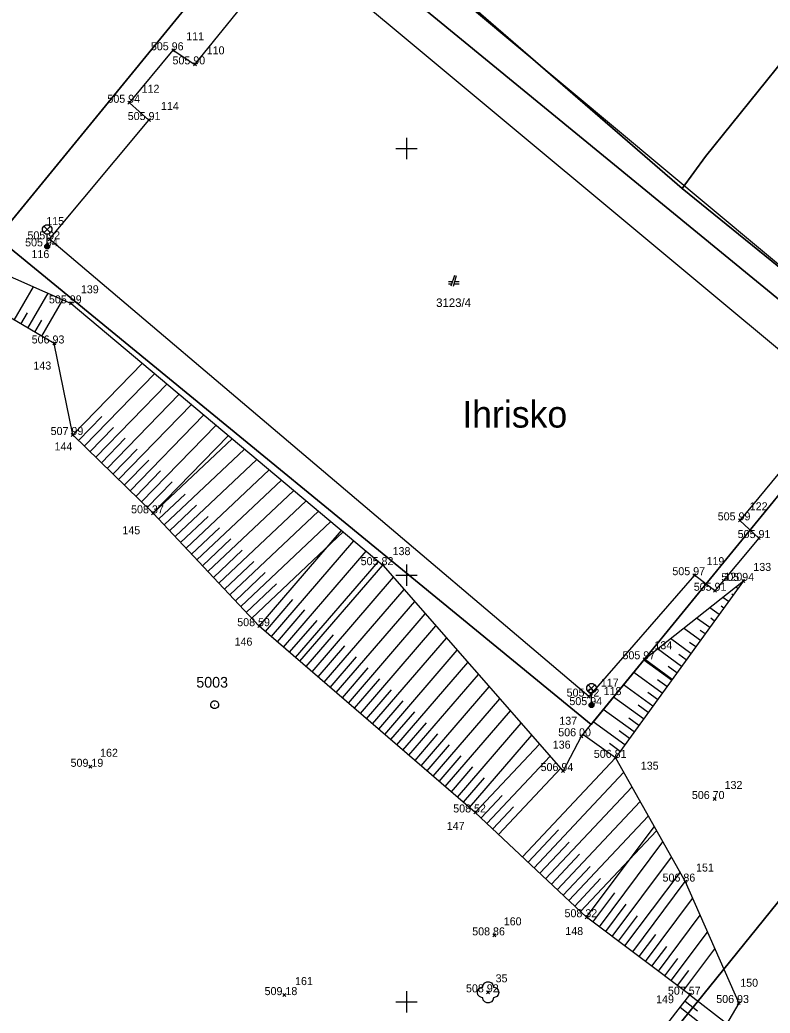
# Model space of a CAD drawing. Extents: x -408550 to -407654, y -1233019 to -1231230.
# Drawn here: x -407958.14 to -407922.95, y -1232060.52 to -1232013.97 of the extents above; entities that cross this region are included whole.
import ezdxf

# ---------------------------------------------------------------- set-up
doc = ezdxf.new("R2010")
doc.units = 0
for name, color, linetype in [('Level 1', 7, 'Continuous'), ('Level 12', 7, 'Continuous'), ('Level 13', 7, 'Continuous'), ('Level 16', 7, 'Continuous'), ('Level 23', 7, 'Continuous'), ('Level 26', 7, 'Continuous'), ('Level 28', 7, 'Continuous'), ('Level 30', 7, 'Continuous'), ('Level 40', 7, 'Continuous'), ('Level 41', 7, 'Continuous'), ('Level 45', 7, 'Continuous')]:
    doc.layers.add(name, color=color, linetype=linetype)

msp = doc.modelspace()

# ---------------------------------------------------------------- linework, layer by layer
at = {"layer": 'Level 1'}
for p, q in [((-407940, -1232019.5), (-407940, -1232020.5)), ((-407940.5, -1232020), (-407939.5, -1232020)), ((-407940, -1232039.5), (-407940, -1232040.5)), ((-407940.5, -1232040), (-407939.5, -1232040)), ((-407940, -1232059.5), (-407940, -1232060.5)), ((-407940.5, -1232060), (-407939.5, -1232060))]:
    msp.add_line(p, q, dxfattribs=at)
for points in [[(-408002.95, -1231959.78), (-407998.58, -1231963.3), (-407985.37, -1231974.5), (-407975.08, -1231982.73), (-407972.21, -1231984.54), (-407969.45, -1231986.76), (-407966.11, -1231989.44), (-407955.64, -1231997.88), (-407939.09, -1232011.47), (-407927.08, -1232021.88), (-407908.02, -1232037.31)], [(-407865.11, -1232098.76), (-407959.41, -1232100.85), (-407908.02, -1232037.31), (-407927.08, -1232021.88), (-407925.98, -1232020.38), (-407922.27, -1232015.79), (-407913.48, -1232004.91), (-407905.89, -1231995.51), (-407896.46, -1231983.85)], [(-407937.755, -1232025.95), (-407937.93, -1232026.45)], [(-407937.805, -1232026.45), (-407937.655, -1232025.95)], [(-407937.86, -1232026.25), (-407938.03, -1232026.25)], [(-407938.03, -1232026.35), (-407937.895, -1232026.35)], [(-407937.775, -1232026.35), (-407937.53, -1232026.35)], [(-407937.53, -1232026.25), (-407937.745, -1232026.25)], [(-407908.02, -1232037.31), (-407959.41, -1232100.85), (-407964.75, -1232098.99), (-407974.67, -1232095.53), (-407985.8, -1232091.65), (-408004.8, -1232085.03), (-408023.96, -1232078.34), (-408035.27, -1232074.4), (-408044.77, -1232071.09)]]:
    msp.add_lwpolyline(points, dxfattribs=at)
for points in [[(-407908.98, -1231973.85), (-407908.6, -1231973.38), (-407908.02, -1231973.41), (-407904.44, -1231976.23), (-407900.26, -1231979.53), (-407895.94, -1231983.2), (-407896.46, -1231983.85), (-407905.89, -1231995.51), (-407913.48, -1232004.91), (-407922.27, -1232015.79), (-407925.98, -1232020.38), (-407927.08, -1232021.88), (-407939.09, -1232011.47)], [(-407945.9, -1232007.95), (-407918.05, -1232030.75), (-407931.35, -1232047), (-407959.2, -1232024.19)], [(-407918.05, -1232030.75), (-407945.9, -1232007.95), (-407959.2, -1232024.19), (-407931.35, -1232047)]]:
    msp.add_lwpolyline(points, close=True, dxfattribs=at)
at = {"layer": 'Level 12'}
msp.add_lwpolyline([(-408056.73, -1232038.31), (-408035.18, -1232049.43), (-408016.67, -1232058.98), (-407995.64, -1232070.23), (-407983.94, -1232082.87), (-407968.55, -1232099.65), (-407955.47, -1232103.17), (-407935.56, -1232108.32), (-407927.78, -1232110.15), (-407922.43, -1232090.45), (-407918.07, -1232073.76), (-407912.71, -1232053.79), (-407910.82, -1232047.19), (-407908.67, -1232042.13), (-407906.88, -1232038.31), (-407908.34, -1232037.12), (-407921.23, -1232026.55), (-407939.09, -1232011.64)], dxfattribs=at)
at = {"layer": 'Level 13'}
for p, q in [((-407958.413, -1232028.044), (-407957.504, -1232026.481)), ((-407957.765, -1232028.421), (-407956.814, -1232026.786)), ((-407957.117, -1232028.799), (-407956.123, -1232027.091)), ((-407958.089, -1232028.233), (-407957.779, -1232027.7)), ((-407957.441, -1232028.61), (-407957.117, -1232028.053)), ((-407955.66, -1232033.43), (-407952.39, -1232030.071)), ((-407955.123, -1232033.953), (-407951.814, -1232030.555)), ((-407954.585, -1232034.476), (-407951.238, -1232031.038)), ((-407954.048, -1232034.999), (-407950.662, -1232031.522)), ((-407953.51, -1232035.523), (-407950.086, -1232032.005)), ((-407955.391, -1232033.692), (-407954.296, -1232032.567)), ((-407952.973, -1232036.046), (-407949.51, -1232032.489)), ((-407954.854, -1232034.215), (-407953.746, -1232033.076)), ((-407952.436, -1232036.569), (-407948.934, -1232032.972)), ((-407954.316, -1232034.738), (-407953.196, -1232033.586)), ((-407951.898, -1232037.092), (-407948.358, -1232033.455)), ((-407951.89, -1232037.1), (-407948.179, -1232033.606)), ((-407953.779, -1232035.261), (-407952.645, -1232034.096)), ((-407951.376, -1232037.646), (-407947.6, -1232034.092)), ((-407953.242, -1232035.784), (-407952.095, -1232034.606)), ((-407950.862, -1232038.192), (-407947.022, -1232034.577)), ((-407952.704, -1232036.307), (-407951.545, -1232035.116)), ((-407950.348, -1232038.738), (-407946.443, -1232035.062)), ((-407952.167, -1232036.831), (-407950.994, -1232035.626)), ((-407949.834, -1232039.284), (-407945.865, -1232035.548)), ((-407951.633, -1232037.373), (-407950.386, -1232036.199)), ((-407949.32, -1232039.83), (-407945.286, -1232036.033)), ((-407948.805, -1232040.377), (-407944.708, -1232036.519)), ((-407951.119, -1232037.919), (-407949.851, -1232036.725)), ((-407948.291, -1232040.923), (-407944.129, -1232037.004)), ((-407950.605, -1232038.465), (-407949.315, -1232037.251)), ((-407947.777, -1232041.469), (-407943.551, -1232037.49)), ((-407950.091, -1232039.011), (-407948.78, -1232037.777)), ((-407947.263, -1232042.015), (-407942.972, -1232037.975)), ((-407946.91, -1232042.39), (-407943.05, -1232037.911)), ((-407949.577, -1232039.557), (-407948.244, -1232038.303)), ((-407946.342, -1232042.88), (-407942.475, -1232038.393)), ((-407949.063, -1232040.103), (-407947.709, -1232038.829)), ((-407945.774, -1232043.369), (-407941.901, -1232038.875)), ((-407948.548, -1232040.65), (-407947.173, -1232039.355)), ((-407945.206, -1232043.859), (-407941.326, -1232039.357)), ((-407948.034, -1232041.196), (-407946.638, -1232039.881)), ((-407945.002, -1232044.034), (-407941.12, -1232039.53)), ((-407944.434, -1232044.524), (-407940.621, -1232040.1)), ((-407947.52, -1232041.742), (-407946.102, -1232040.407)), ((-407943.866, -1232045.014), (-407940.121, -1232040.669)), ((-407924.461, -1232040.63), (-407924.562, -1232040.557)), ((-407946.626, -1232042.635), (-407945.339, -1232041.142)), ((-407943.297, -1232045.503), (-407939.622, -1232041.239)), ((-407924.901, -1232041.237), (-407925.173, -1232041.04)), ((-407924.681, -1232040.934), (-407924.743, -1232040.889)), ((-407946.058, -1232043.124), (-407944.769, -1232041.629)), ((-407925.341, -1232041.845), (-407925.785, -1232041.523)), ((-407925.121, -1232041.541), (-407925.24, -1232041.455)), ((-407945.49, -1232043.614), (-407944.199, -1232042.116)), ((-407942.729, -1232045.993), (-407939.123, -1232041.808)), ((-407925.782, -1232042.452), (-407926.396, -1232042.007)), ((-407925.562, -1232042.148), (-407925.738, -1232042.021)), ((-407942.161, -1232046.482), (-407938.624, -1232042.378)), ((-407926.222, -1232043.059), (-407927.007, -1232042.49)), ((-407926.002, -1232042.755), (-407926.235, -1232042.587)), ((-407944.718, -1232044.279), (-407943.437, -1232042.793)), ((-407941.593, -1232046.972), (-407938.124, -1232042.947)), ((-407926.662, -1232043.666), (-407927.618, -1232042.973)), ((-407926.442, -1232043.363), (-407926.732, -1232043.152)), ((-407944.15, -1232044.769), (-407942.891, -1232043.309)), ((-407941.025, -1232047.462), (-407937.625, -1232043.517)), ((-407927.102, -1232044.273), (-407928.229, -1232043.457)), ((-407943.582, -1232045.258), (-407942.346, -1232043.825)), ((-407940.457, -1232047.951), (-407937.126, -1232044.086)), ((-407927.569, -1232044.917), (-407928.868, -1232043.975)), ((-407927.543, -1232044.881), (-407928.84, -1232043.94)), ((-407926.882, -1232043.97), (-407927.229, -1232043.718)), ((-407943.013, -1232045.748), (-407941.801, -1232044.341)), ((-407928.009, -1232045.524), (-407929.345, -1232044.556)), ((-407927.322, -1232044.577), (-407927.726, -1232044.284)), ((-407942.445, -1232046.238), (-407941.256, -1232044.857)), ((-407939.889, -1232048.441), (-407936.626, -1232044.656)), ((-407927.789, -1232045.22), (-407928.228, -1232044.902)), ((-407941.877, -1232046.727), (-407940.711, -1232045.374)), ((-407939.321, -1232048.931), (-407936.127, -1232045.225)), ((-407928.449, -1232046.131), (-407929.821, -1232045.137)), ((-407928.229, -1232045.828), (-407928.68, -1232045.501)), ((-407941.309, -1232047.217), (-407940.165, -1232045.89)), ((-407938.752, -1232049.42), (-407935.628, -1232045.795)), ((-407928.889, -1232046.738), (-407930.297, -1232045.718)), ((-407940.741, -1232047.707), (-407939.62, -1232046.406)), ((-407938.184, -1232049.91), (-407935.129, -1232046.364)), ((-407929.33, -1232047.346), (-407930.774, -1232046.299)), ((-407928.669, -1232046.435), (-407929.132, -1232046.099)), ((-407929.77, -1232047.953), (-407931.25, -1232046.88)), ((-407929.109, -1232047.042), (-407929.584, -1232046.698)), ((-407940.173, -1232048.196), (-407939.075, -1232046.922)), ((-407937.616, -1232050.399), (-407934.629, -1232046.934)), ((-407929.55, -1232047.649), (-407930.037, -1232047.296)), ((-407939.605, -1232048.686), (-407938.53, -1232047.439)), ((-407937.048, -1232050.889), (-407934.13, -1232047.503)), ((-407930.21, -1232048.56), (-407931.727, -1232047.46)), ((-407939.036, -1232049.175), (-407937.985, -1232047.955)), ((-407936.78, -1232051.12), (-407933.767, -1232047.917)), ((-407929.99, -1232048.256), (-407930.489, -1232047.895)), ((-407938.468, -1232049.665), (-407937.439, -1232048.471)), ((-407936.234, -1232051.634), (-407933.271, -1232048.484)), ((-407934.572, -1232053.197), (-407930.21, -1232048.56)), ((-407937.9, -1232050.155), (-407936.894, -1232048.987)), ((-407935.687, -1232052.148), (-407932.774, -1232049.05)), ((-407937.332, -1232050.644), (-407936.349, -1232049.503)), ((-407934.025, -1232053.711), (-407929.823, -1232049.244)), ((-407933.479, -1232054.225), (-407929.437, -1232049.927)), ((-407936.507, -1232051.377), (-407935.512, -1232050.319)), ((-407932.933, -1232054.739), (-407929.05, -1232050.611)), ((-407935.961, -1232051.891), (-407934.982, -1232050.851)), ((-407932.387, -1232055.253), (-407928.664, -1232051.295)), ((-407934.299, -1232053.454), (-407932.873, -1232051.938)), ((-407931.84, -1232055.766), (-407928.277, -1232051.978)), ((-407931.56, -1232056.03), (-407928.385, -1232051.788)), ((-407933.752, -1232053.968), (-407932.38, -1232052.509)), ((-407930.96, -1232056.479), (-407927.982, -1232052.501)), ((-407933.206, -1232054.482), (-407931.886, -1232053.079)), ((-407930.359, -1232056.929), (-407927.578, -1232053.213)), ((-407932.66, -1232054.996), (-407931.393, -1232053.649)), ((-407932.113, -1232055.509), (-407930.9, -1232054.22)), ((-407929.759, -1232057.378), (-407927.175, -1232053.926)), ((-407929.394, -1232057.651), (-407926.93, -1232054.36)), ((-407931.26, -1232056.255), (-407930.235, -1232054.886)), ((-407928.793, -1232058.101), (-407926.583, -1232055.148)), ((-407930.659, -1232056.704), (-407929.701, -1232055.423)), ((-407930.059, -1232057.154), (-407929.166, -1232055.96)), ((-407928.193, -1232058.55), (-407926.235, -1232055.935)), ((-407929.093, -1232057.876), (-407928.315, -1232056.836)), ((-407927.592, -1232059), (-407925.888, -1232056.723)), ((-407928.493, -1232058.326), (-407927.799, -1232057.398)), ((-407926.992, -1232059.449), (-407925.54, -1232057.51)), ((-407927.892, -1232058.775), (-407927.283, -1232057.96)), ((-407927.292, -1232059.224), (-407926.767, -1232058.522)), ((-407926.71, -1232059.66), (-407924.98, -1232061.003)), ((-407927.17, -1232060.252), (-407925.364, -1232061.655)), ((-407926.94, -1232059.956), (-407926.351, -1232060.413))]:
    msp.add_line(p, q, dxfattribs=at)
msp.add_lwpolyline([(-407928.84, -1232043.94), (-407924.2, -1232040.27), (-407930.21, -1232048.56), (-407926.93, -1232054.36), (-407924.42, -1232060.05), (-407929, -1232067.84), (-407940.94, -1232074.95), (-407931.23, -1232065.48), (-407926.71, -1232059.66), (-407931.56, -1232056.03), (-407936.78, -1232051.12), (-407946.91, -1232042.39), (-407951.89, -1232037.1), (-407955.66, -1232033.43), (-407956.53, -1232029.14), (-407959.71, -1232027.29), (-407963.37, -1232025.1), (-407959.59, -1232025.56), (-407955.74, -1232027.26), (-407941.12, -1232039.53), (-407932.66, -1232049.18), (-407931.8, -1232047.55)], close=True, dxfattribs=at)
at = {"layer": 'Level 16'}
msp.add_lwpolyline([(-407919.7, -1232031.78), (-407924.37, -1232037.43), (-407923.48, -1232038.26), (-407925.54, -1232040.73), (-407926.5, -1232040), (-407931.46, -1232045.69), (-407956.75, -1232024.26), (-407952.09, -1232018.67), (-407953, -1232017.86), (-407950.95, -1232015.4), (-407949.93, -1232016.06), (-407945.35, -1232010.41)], close=True, dxfattribs=at)
at = {"layer": 'Level 23'}
for points in [[(-407950.881, -1232015.469), (-407951.019, -1232015.331)], [(-407951.019, -1232015.469), (-407950.881, -1232015.331)], [(-407949.861, -1232016.129), (-407949.999, -1232015.991)], [(-407949.999, -1232016.129), (-407949.861, -1232015.991)], [(-407952.931, -1232017.929), (-407953.069, -1232017.791)], [(-407953.069, -1232017.929), (-407952.931, -1232017.791)], [(-407952.021, -1232018.739), (-407952.159, -1232018.601)], [(-407952.159, -1232018.739), (-407952.021, -1232018.601)], [(-407956.791, -1232024.659), (-407956.929, -1232024.521)], [(-407956.929, -1232024.659), (-407956.791, -1232024.521)], [(-407956.681, -1232024.329), (-407956.819, -1232024.191)], [(-407956.819, -1232024.329), (-407956.681, -1232024.191)], [(-407955.671, -1232027.329), (-407955.809, -1232027.191)], [(-407955.809, -1232027.329), (-407955.671, -1232027.191)], [(-407956.461, -1232029.209), (-407956.599, -1232029.071)], [(-407956.599, -1232029.209), (-407956.461, -1232029.071)], [(-407955.591, -1232033.499), (-407955.729, -1232033.361)], [(-407955.729, -1232033.499), (-407955.591, -1232033.361)], [(-407951.821, -1232037.169), (-407951.959, -1232037.031)], [(-407951.959, -1232037.169), (-407951.821, -1232037.031)], [(-407924.301, -1232037.499), (-407924.439, -1232037.361)], [(-407924.439, -1232037.499), (-407924.301, -1232037.361)], [(-407923.411, -1232038.329), (-407923.549, -1232038.191)], [(-407923.549, -1232038.329), (-407923.411, -1232038.191)], [(-407941.051, -1232039.599), (-407941.189, -1232039.461)], [(-407941.189, -1232039.599), (-407941.051, -1232039.461)], [(-407926.431, -1232040.069), (-407926.569, -1232039.931)], [(-407926.569, -1232040.069), (-407926.431, -1232039.931)], [(-407924.131, -1232040.339), (-407924.269, -1232040.201)], [(-407924.269, -1232040.339), (-407924.131, -1232040.201)], [(-407925.471, -1232040.799), (-407925.609, -1232040.661)], [(-407925.609, -1232040.799), (-407925.471, -1232040.661)], [(-407946.841, -1232042.459), (-407946.979, -1232042.321)], [(-407946.979, -1232042.459), (-407946.841, -1232042.321)], [(-407928.771, -1232044.009), (-407928.909, -1232043.871)], [(-407928.909, -1232044.009), (-407928.771, -1232043.871)], [(-407931.391, -1232045.759), (-407931.529, -1232045.621)], [(-407931.529, -1232045.759), (-407931.391, -1232045.621)], [(-407931.261, -1232046.159), (-407931.399, -1232046.021)], [(-407931.399, -1232046.159), (-407931.261, -1232046.021)], [(-407931.731, -1232047.619), (-407931.869, -1232047.481)], [(-407931.869, -1232047.619), (-407931.731, -1232047.481)], [(-407930.141, -1232048.629), (-407930.279, -1232048.491)], [(-407930.279, -1232048.629), (-407930.141, -1232048.491)], [(-407954.761, -1232049.049), (-407954.899, -1232048.911)], [(-407954.899, -1232049.049), (-407954.761, -1232048.911)], [(-407932.591, -1232049.249), (-407932.729, -1232049.111)], [(-407932.729, -1232049.249), (-407932.591, -1232049.111)], [(-407925.481, -1232050.559), (-407925.619, -1232050.421)], [(-407925.619, -1232050.559), (-407925.481, -1232050.421)], [(-407936.711, -1232051.189), (-407936.849, -1232051.051)], [(-407936.849, -1232051.189), (-407936.711, -1232051.051)], [(-407926.861, -1232054.429), (-407926.999, -1232054.291)], [(-407926.999, -1232054.429), (-407926.861, -1232054.291)], [(-407931.491, -1232056.099), (-407931.629, -1232055.961)], [(-407931.629, -1232056.099), (-407931.491, -1232055.961)], [(-407935.811, -1232056.949), (-407935.949, -1232056.811)], [(-407935.949, -1232056.949), (-407935.811, -1232056.811)], [(-407945.661, -1232059.749), (-407945.799, -1232059.611)], [(-407945.799, -1232059.749), (-407945.661, -1232059.611)], [(-407936.111, -1232059.619), (-407936.249, -1232059.481)], [(-407936.249, -1232059.619), (-407936.111, -1232059.481)], [(-407926.641, -1232059.729), (-407926.779, -1232059.591)], [(-407926.779, -1232059.729), (-407926.641, -1232059.591)], [(-407924.351, -1232060.119), (-407924.489, -1232059.981)], [(-407924.489, -1232060.119), (-407924.351, -1232059.981)]]:
    msp.add_lwpolyline(points, dxfattribs=at)
at = {"layer": 'Level 28'}
msp.add_lwpolyline([(-407935.68, -1232059.55), (-407935.705, -1232059.659), (-407935.774, -1232059.746), (-407935.874, -1232059.794), (-407935.93, -1232059.8), (-407935.955, -1232059.909), (-407936.024, -1232059.996), (-407936.124, -1232060.044), (-407936.236, -1232060.044), (-407936.336, -1232059.996), (-407936.405, -1232059.909), (-407936.43, -1232059.8), (-407936.486, -1232059.794), (-407936.586, -1232059.746), (-407936.655, -1232059.659), (-407936.68, -1232059.55), (-407936.655, -1232059.442), (-407936.586, -1232059.355), (-407936.486, -1232059.306), (-407936.43, -1232059.3), (-407936.405, -1232059.192), (-407936.336, -1232059.105), (-407936.236, -1232059.056), (-407936.124, -1232059.056), (-407936.024, -1232059.105), (-407935.955, -1232059.192), (-407935.93, -1232059.3), (-407935.874, -1232059.306), (-407935.774, -1232059.355), (-407935.705, -1232059.442)], close=True, dxfattribs=at)
msp.add_lwpolyline([(-407936.192, -1232059.55), (-407936.18, -1232059.55), (-407936.168, -1232059.55)], dxfattribs=at)
at = {"layer": 'Level 30'}
msp.add_lwpolyline([(-407948.962, -1232045.889), (-407948.878, -1232045.938), (-407948.829, -1232046.022), (-407948.829, -1232046.118), (-407948.878, -1232046.203), (-407948.962, -1232046.251), (-407949.058, -1232046.251), (-407949.142, -1232046.203), (-407949.191, -1232046.118), (-407949.191, -1232046.022), (-407949.142, -1232045.938), (-407949.058, -1232045.889)], close=True, dxfattribs=at)
msp.add_lwpolyline([(-407949.022, -1232046.07), (-407948.998, -1232046.07)], dxfattribs=at)
at = {"layer": 'Level 45'}
for points in [[(-407956.86, -1232024.479), (-407956.86, -1232024.012), (-407956.918, -1232024.012), (-407957.016, -1232023.954), (-407957.077, -1232023.853), (-407957.077, -1232023.737), (-407957.019, -1232023.636), (-407956.918, -1232023.578), (-407956.802, -1232023.578), (-407956.701, -1232023.636), (-407956.643, -1232023.737), (-407956.643, -1232023.853), (-407956.71, -1232023.96), (-407956.802, -1232024.012), (-407956.86, -1232024.012)], [(-407956.71, -1232023.96), (-407957.019, -1232023.636)], [(-407957.016, -1232023.954), (-407956.701, -1232023.636)], [(-407956.86, -1232024.479), (-407956.814, -1232024.479), (-407956.749, -1232024.544), (-407956.749, -1232024.636), (-407956.814, -1232024.701), (-407956.906, -1232024.701), (-407956.971, -1232024.636), (-407956.971, -1232024.544), (-407956.906, -1232024.479), (-407956.86, -1232024.479), (-407956.814, -1232024.491), (-407956.903, -1232024.492), (-407956.92, -1232024.506), (-407956.8, -1232024.506), (-407956.776, -1232024.53), (-407956.944, -1232024.53), (-407956.957, -1232024.554), (-407956.763, -1232024.554), (-407956.763, -1232024.578), (-407956.957, -1232024.579), (-407956.957, -1232024.602), (-407956.762, -1232024.603), (-407956.762, -1232024.626), (-407956.955, -1232024.626), (-407956.944, -1232024.65), (-407956.776, -1232024.65), (-407956.8, -1232024.674), (-407956.92, -1232024.674), (-407956.906, -1232024.687), (-407956.812, -1232024.687)], [(-407931.33, -1232045.979), (-407931.33, -1232045.512), (-407931.388, -1232045.512), (-407931.486, -1232045.454), (-407931.547, -1232045.353), (-407931.547, -1232045.237), (-407931.489, -1232045.136), (-407931.388, -1232045.078), (-407931.272, -1232045.078), (-407931.171, -1232045.136), (-407931.113, -1232045.237), (-407931.113, -1232045.353), (-407931.18, -1232045.46), (-407931.272, -1232045.512), (-407931.33, -1232045.512)], [(-407931.18, -1232045.46), (-407931.489, -1232045.136)], [(-407931.486, -1232045.454), (-407931.171, -1232045.136)], [(-407931.33, -1232045.979), (-407931.284, -1232045.979), (-407931.219, -1232046.044), (-407931.219, -1232046.136), (-407931.284, -1232046.201), (-407931.376, -1232046.201), (-407931.441, -1232046.136), (-407931.441, -1232046.044), (-407931.376, -1232045.979), (-407931.33, -1232045.979), (-407931.284, -1232045.991), (-407931.373, -1232045.992), (-407931.39, -1232046.006), (-407931.27, -1232046.006), (-407931.246, -1232046.03), (-407931.414, -1232046.03), (-407931.427, -1232046.054), (-407931.233, -1232046.054), (-407931.233, -1232046.078), (-407931.428, -1232046.079), (-407931.427, -1232046.102), (-407931.233, -1232046.103), (-407931.233, -1232046.126), (-407931.425, -1232046.126), (-407931.414, -1232046.15), (-407931.246, -1232046.15), (-407931.27, -1232046.174), (-407931.39, -1232046.174), (-407931.376, -1232046.187), (-407931.282, -1232046.187)]]:
    msp.add_lwpolyline(points, dxfattribs=at)

# ---------------------------------------------------------------- texts
at = {"layer": 'Level 1'}
msp.add_text('3123/4', height=0.4, dxfattribs=at).set_placement((-407938.615, -1232027.43))
at = {"layer": 'Level 26'}
for s, p in [('111', (-407950.337, -1232014.93)), ('110', (-407949.377, -1232015.59)), ('112', (-407952.431, -1232017.39)), ('114', (-407951.521, -1232018.2)), ('115', (-407956.903, -1232023.595)), ('116', (-407957.596, -1232025.139)), ('139', (-407955.279, -1232026.79)), ('143', (-407957.506, -1232030.364)), ('144', (-407956.515, -1232034.152)), ('122', (-407923.907, -1232036.96)), ('145', (-407953.332, -1232038.081)), ('138', (-407940.657, -1232039.06)), ('119', (-407925.932, -1232039.53)), ('133', (-407923.737, -1232039.8)), ('120', (-407925.093, -1232040.26)), ('146', (-407948.07, -1232043.302)), ('134', (-407928.377, -1232043.47)), ('117', (-407930.891, -1232045.22)), ('118', (-407930.761, -1232045.62)), ('137', (-407932.836, -1232047.011)), ('136', (-407933.146, -1232048.129)), ('162', (-407954.378, -1232048.51)), ('135', (-407929.016, -1232049.114)), ('132', (-407925.087, -1232050.02)), ('147', (-407938.116, -1232051.937)), ('151', (-407926.423, -1232053.89)), ('160', (-407935.444, -1232056.41)), ('148', (-407932.556, -1232056.864)), ('161', (-407945.233, -1232059.21)), ('35', (-407935.826, -1232059.08)), ('150', (-407924.352, -1232059.288)), ('149', (-407928.297, -1232060.06))]:
    msp.add_text(s, height=0.375, dxfattribs=at).set_placement(p)
at = {"layer": 'Level 28'}
msp.add_text('Ihrisko', height=1.25, dxfattribs=at).set_placement((-407937.391, -1232033.082))
at = {"layer": 'Level 40'}
for s, p in [('505 96', (-407951.996, -1232015.4)), ('505 90', (-407950.982, -1232016.06)), ('505 94', (-407954.035, -1232017.86)), ('505 91', (-407953.081, -1232018.67)), ('505 92', (-407957.785, -1232024.26)), ('505 94', (-407957.895, -1232024.59)), ('505 99', (-407956.777, -1232027.26)), ('506 93', (-407957.586, -1232029.14)), ('507 99', (-407956.697, -1232033.43)), ('508 37', (-407952.924, -1232037.1)), ('505 99', (-407925.407, -1232037.43)), ('505 91', (-407924.471, -1232038.26)), ('505 82', (-407942.154, -1232039.53)), ('505 97', (-407927.535, -1232040)), ('505 94', (-407925.235, -1232040.27)), ('505 91', (-407926.531, -1232040.73)), ('508 59', (-407947.945, -1232042.39)), ('505 97', (-407929.875, -1232043.94)), ('505 92', (-407932.495, -1232045.69)), ('505 94', (-407932.365, -1232046.09)), ('506 00', (-407932.887, -1232047.55)), ('506 81', (-407931.22, -1232048.56)), ('509 19', (-407955.762, -1232048.98)), ('506 94', (-407933.716, -1232049.18)), ('506 70', (-407926.621, -1232050.49)), ('508 52', (-407937.814, -1232051.12)), ('506 86', (-407927.995, -1232054.36)), ('508 32', (-407932.594, -1232056.03)), ('508 86', (-407936.924, -1232056.88)), ('509 18', (-407946.661, -1232059.68)), ('508 92', (-407937.215, -1232059.55)), ('507 57', (-407927.744, -1232059.66)), ('506 93', (-407925.476, -1232060.05))]:
    msp.add_text(s, height=0.375, dxfattribs=at).set_placement(p)
at = {"layer": 'Level 41'}
msp.add_text('5003', height=0.5, dxfattribs=at).set_placement((-407949.865, -1232045.269))

doc.saveas('drawing.dxf')
